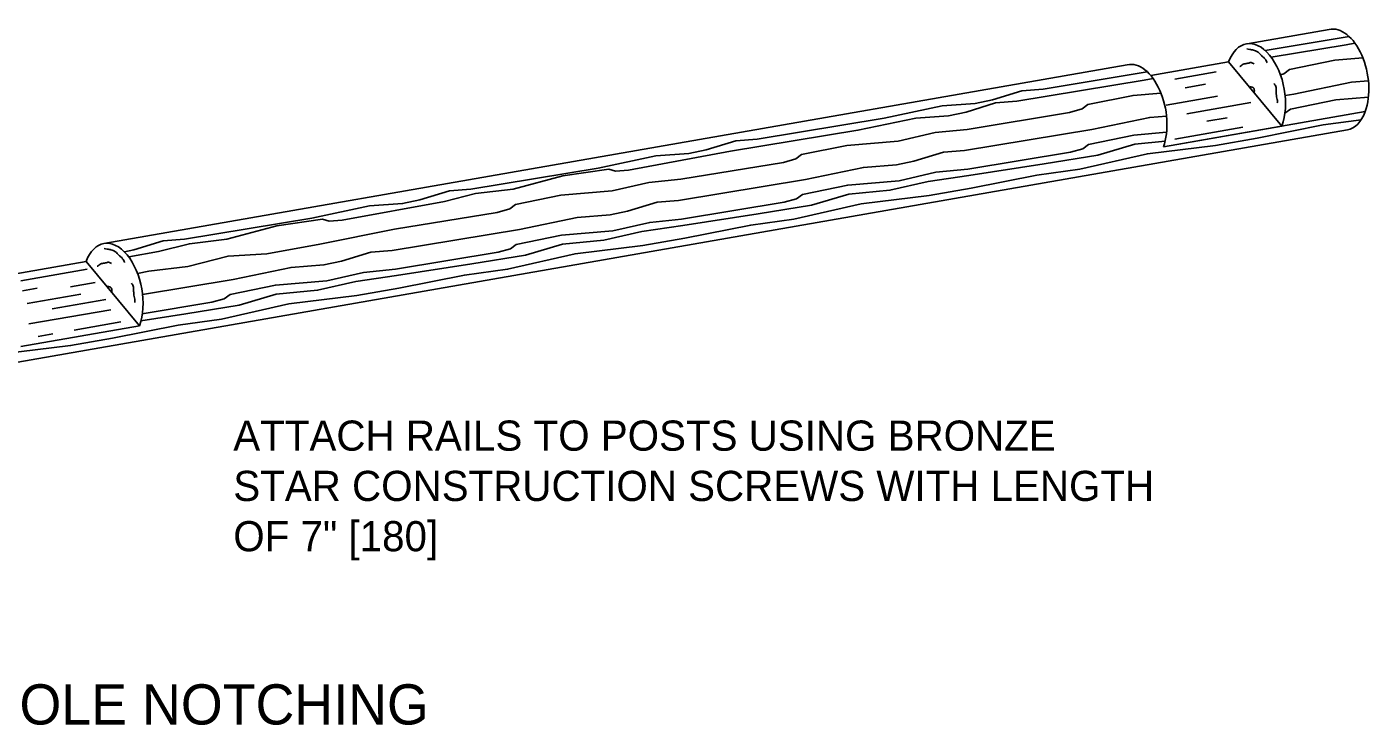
# Model space of a CAD drawing. Extents: x 49991 to 50288, y 49919 to 50011.
# Drawn here: x 50131.11 to 50150.21, y 49960.39 to 49970.31 of the extents above; entities that cross this region are included whole.
import ezdxf

# ---------------------------------------------------------------- set-up
doc = ezdxf.new("R2010")
doc.units = 0
doc.layers.add('Level 1', color=7, linetype='Continuous')
doc.layers.add('Level 2', color=7, linetype='Continuous')

msp = doc.modelspace()

# ---------------------------------------------------------------- linework, layer by layer
at = {"layer": 'Level 1'}
for p, q in [((50148.45032095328, 49970.06973190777), (50149.616370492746, 49970.27344752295)), ((50132.20796831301, 49967.23209650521), (50146.74800530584, 49969.772325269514)), ((50148.18814838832, 49969.811157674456), (50147.083473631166, 49969.618284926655)), ((50147.08368423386, 49969.618209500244), (50148.18814838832, 49969.811157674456)), ((50148.18828656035, 49969.8111817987), (50148.9467034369, 49968.90097008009)), ((50147.42499742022, 49969.56718812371), (50148.01425804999, 49969.67006959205)), ((50147.57207015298, 49969.445268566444), (50147.861148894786, 49969.49553878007)), ((50147.30407706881, 49969.198929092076), (50148.030781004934, 49969.32585033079)), ((50147.596818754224, 49969.07687578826), (50148.50698885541, 49969.23559233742)), ((50147.262093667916, 49968.606609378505), (50150.130656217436, 49969.10774276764)), ((50147.87966226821, 49968.969568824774), (50148.168741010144, 49969.019839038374)), ((50113.90505239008, 49962.567250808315), (50149.87663416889, 49968.84808164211)), ((50147.262056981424, 49968.606677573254), (50148.9467034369, 49968.90097008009)), ((50147.42451887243, 49968.716225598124), (50148.39337950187, 49968.8854457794)), ((50131.954379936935, 49966.97514372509), (50130.84970517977, 49966.78227097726)), ((50131.96889181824, 49966.86947742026), (50131.02839103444, 49966.70487244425)), ((50131.95451810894, 49966.97516784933), (50132.712934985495, 49966.06495613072)), ((50132.08617606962, 49966.678574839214), (50131.73579811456, 49966.617650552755)), ((50131.26102300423, 49966.59721857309), (50131.05133796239, 49966.56090967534)), ((50131.881565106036, 49966.513987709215), (50131.116986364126, 49966.38074882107)), ((50132.23741644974, 49966.439771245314), (50131.47522511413, 49966.306308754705)), ((50132.30510708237, 49966.293204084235), (50131.141221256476, 49966.08991450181)), ((50131.02828853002, 49965.77066362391), (50132.712934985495, 49966.06495613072)), ((50132.44856788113, 49966.11945066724), (50131.7866710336, 49966.00354967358)), ((50131.484160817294, 49965.94833130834), (50131.27473404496, 49965.911812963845))]:
    msp.add_line(p, q, dxfattribs=at)
for points in [[(50148.70739651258, 49969.97515538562), (50149.902069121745, 49970.172291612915)], [(50148.79570268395, 49969.8778573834), (50149.857548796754, 49970.05298712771), (50149.983376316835, 49970.07959688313)], [(50148.92511135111, 49969.63103608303), (50148.97486510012, 49969.64477204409), (50149.0563922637, 49969.70623738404), (50149.70032202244, 49969.83799336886), (50150.09613885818, 49969.87127311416)], [(50145.18110421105, 49969.25368066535), (50146.988986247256, 49969.551853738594), (50147.114813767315, 49969.57846349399)], [(50145.55565291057, 49969.42729350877), (50147.03350657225, 49969.6711582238)], [(50148.99181456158, 49969.334903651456), (50149.11338977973, 49969.35497671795), (50149.93641159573, 49969.52623111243), (50150.17539683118, 49969.544558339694)], [(50141.48827417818, 49968.71619301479), (50143.29629242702, 49969.0153259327), (50144.118637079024, 49969.18627323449), (50144.58559179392, 49969.22201420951), (50144.8330862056, 49969.27432659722), (50145.251976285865, 49969.40363187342), (50145.55565291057, 49969.42729350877)], [(50144.47193565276, 49968.854594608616), (50145.93005781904, 49969.09498120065), (50146.1063025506, 49969.14363865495), (50146.1878297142, 49969.20510399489), (50146.83175947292, 49969.336859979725), (50147.22757630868, 49969.37013972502)], [(50148.98955932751, 49969.08277762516), (50149.068641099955, 49969.14274059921), (50149.71308739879, 49969.27407769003), (50150.17617772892, 49969.31325724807)], [(50141.11367665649, 49968.54304788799), (50142.92148545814, 49968.841922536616), (50143.74383011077, 49969.0128698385), (50144.21106750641, 49969.048167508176), (50144.45832805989, 49969.10045548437), (50144.87789530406, 49969.23006785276), (50145.18110421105, 49969.25368066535)], [(50144.43837275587, 49968.555582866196), (50146.24482723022, 49968.853843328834), (50147.06784904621, 49969.02509772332), (50147.30683428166, 49969.04342495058)], [(50148.59656793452, 49968.729591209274), (50149.53098348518, 49968.91625600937), (50150.0720112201, 49968.98975277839)], [(50140.40583801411, 49968.14480987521), (50141.86398459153, 49968.384962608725), (50142.039478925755, 49968.43401454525), (50142.12173207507, 49968.495319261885), (50142.765637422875, 49968.62730910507), (50143.4958781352, 49968.68864208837), (50144.0193219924, 49968.80829389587), (50144.47193565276, 49968.854594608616)], [(50144.48423331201, 49968.29063010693), (50145.94144445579, 49968.530685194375), (50146.118366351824, 49968.57964974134), (50146.200078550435, 49968.64160721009), (50146.84452484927, 49968.772944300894), (50147.3076151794, 49968.81212385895)], [(50144.530567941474, 49968.01887104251), (50145.46428191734, 49968.20546260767), (50146.076036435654, 49968.289888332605), (50147.03514231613, 49968.507262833), (50148.00125139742, 49968.62584118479), (50148.59656793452, 49968.729591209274)], [(50141.11367665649, 49968.54304788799), (50139.660773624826, 49968.2753101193), (50139.47764198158, 49968.26092194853), (50139.38074789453, 49968.29005110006), (50138.73005718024, 49968.195887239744), (50138.02189552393, 49968.00683535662), (50137.48894883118, 49967.94198354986), (50137.047959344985, 49967.83188441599)], [(50137.4214261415, 49968.00680276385), (50139.22954203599, 49968.305000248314), (50140.05181345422, 49968.476649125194), (50140.51834927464, 49968.51187356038), (50140.76589250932, 49968.56371823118), (50141.1854597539, 49968.69333059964), (50141.48827417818, 49968.71619301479)], [(50140.37141291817, 49967.844998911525), (50142.17934377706, 49968.142704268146), (50143.00112306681, 49968.31453818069), (50143.46815101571, 49968.34957758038), (50143.71554778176, 49968.40282540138), (50144.135914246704, 49968.531575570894), (50144.43837275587, 49968.555582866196)], [(50144.499317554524, 49968.20047892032), (50145.570655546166, 49968.36408420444), (50146.32978476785, 49968.486115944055), (50146.85619207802, 49968.64532058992), (50147.28593578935, 49968.68515441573)], [(50140.41753174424, 49967.57983670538), (50141.87476729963, 49967.819657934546), (50142.05140651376, 49967.86906578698), (50142.1339179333, 49967.93016105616), (50142.777540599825, 49968.06259420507), (50143.50752304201, 49968.12413663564), (50144.03070862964, 49968.24399788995), (50144.48423331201, 49968.29063010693)], [(50140.43259157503, 49967.48991937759), (50141.50346184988, 49967.653475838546), (50142.263477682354, 49967.77607294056), (50142.790586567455, 49967.93535082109), (50143.37697359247, 49967.98875975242), (50143.920309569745, 49968.1126156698), (50144.499317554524, 49968.20047892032)], [(50133.35451512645, 49967.29575109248), (50135.162372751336, 49967.59415802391), (50135.9845953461, 49967.76627461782), (50136.451204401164, 49967.8007974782), (50136.6991177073, 49967.85362640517), (50137.11824164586, 49967.98295609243), (50137.4214261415, 49968.00680276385)], [(50136.339506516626, 49967.435000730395), (50137.79749247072, 49967.67442747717), (50137.97405845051, 49967.724536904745), (50138.05542498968, 49967.78527625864), (50138.699539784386, 49967.91752437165), (50139.42975608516, 49967.97909121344), (50139.95324876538, 49968.09827530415), (50140.40583801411, 49968.14480987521)], [(50140.46451912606, 49967.30861859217), (50141.39849137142, 49967.49500071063), (50142.0097781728, 49967.57937761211), (50142.96878640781, 49967.797687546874), (50143.93426714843, 49967.915491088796), (50144.530567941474, 49968.01887104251)], [(50137.047959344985, 49967.83188441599), (50135.593887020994, 49967.56402458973), (50135.411432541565, 49967.549943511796), (50135.31500617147, 49967.57912148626), (50134.66413042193, 49967.48446549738), (50133.95568608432, 49967.29585691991), (50133.423538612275, 49967.2301429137), (50132.98247589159, 49967.12074535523)], [(50136.30380032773, 49967.13387400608), (50138.111584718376, 49967.43298251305), (50138.934630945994, 49967.60400304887), (50139.40161007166, 49967.639510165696), (50139.64926510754, 49967.69254853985), (50140.06843786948, 49967.82141051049), (50140.37141291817, 49967.844998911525)], [(50136.339506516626, 49967.435000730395), (50135.27679254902, 49967.225014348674), (50134.52167214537, 49967.08496135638), (50133.97257159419, 49967.05482993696), (50133.40128932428, 49966.906543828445), (50132.84835286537, 49966.83842334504), (50132.68714974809, 49966.80646604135)], [(50136.351039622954, 49966.8693015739), (50137.80822635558, 49967.10959051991), (50137.985284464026, 49967.15951491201), (50138.067586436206, 49967.220351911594), (50138.71104847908, 49967.35205907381), (50139.44124036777, 49967.41385977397), (50139.96449919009, 49967.53301945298), (50140.41753174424, 49967.57983670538)], [(50136.36680102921, 49966.779457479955), (50137.437227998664, 49966.94273126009), (50138.197219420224, 49967.065562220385), (50138.723675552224, 49967.22429914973), (50139.310101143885, 49967.27960335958), (50139.854051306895, 49967.40210494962), (50140.43259157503, 49967.48991937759)], [(50132.499412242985, 49967.11476491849), (50132.63241613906, 49967.14283300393), (50133.051306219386, 49967.27213827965), (50133.35451512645, 49967.29575109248)], [(50136.39870416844, 49966.598390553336), (50137.33174098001, 49966.784675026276), (50137.94345693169, 49966.86720547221), (50138.90273759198, 49967.08743509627), (50139.867984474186, 49967.20521422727), (50140.46451912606, 49967.30861859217)], [(50132.98247589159, 49967.12074535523), (50132.56102159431, 49967.04318186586)], [(50132.75715391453, 49966.50951816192), (50134.04623747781, 49966.72280329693), (50134.86904984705, 49966.89379942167), (50135.33556125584, 49966.929257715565), (50135.58298243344, 49966.982271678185), (50136.00171188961, 49967.11085096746), (50136.30380032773, 49967.13387400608)], [(50132.75443597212, 49966.23644659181), (50133.74287911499, 49966.39941130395), (50133.91928447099, 49966.44879474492), (50134.00067542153, 49966.509300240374), (50134.64476580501, 49966.64178221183), (50135.37477265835, 49966.70309078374), (50135.8987086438, 49966.822557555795), (50136.351039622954, 49966.8693015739)], [(50132.73471223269, 49966.13510606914), (50133.37076028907, 49966.23196226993), (50134.13062965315, 49966.355962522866), (50134.656740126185, 49966.51348133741), (50135.24452004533, 49966.56939973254), (50135.78826076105, 49966.69164305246), (50136.36680102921, 49966.779457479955)], [(50132.33078448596, 49965.88794281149), (50133.26548271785, 49966.07416430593), (50133.87756874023, 49966.157679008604), (50134.83678642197, 49966.37624721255), (50135.80219392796, 49966.49475232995), (50136.39870416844, 49966.598390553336)], [(50128.26501835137, 49965.177247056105), (50129.19945831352, 49965.36367799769), (50129.8097608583, 49965.44842497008), (50130.769358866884, 49965.665614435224), (50131.7343230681, 49965.783836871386), (50132.33078448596, 49965.88794281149)]]:
    msp.add_lwpolyline(points, dxfattribs=at)
for centre, start_param, end_param in [((50149.7510591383, 49969.561881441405), 3.9254893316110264, 6.306125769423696), ((50148.56712636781, 49969.354986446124), 3.9256121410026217, 7.063370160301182), ((50146.88249658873, 49969.06074805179), 3.9254893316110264, 6.306125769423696), ((50149.75087589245, 49969.561380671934), 3.1414661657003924, 3.926391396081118), ((50132.33335791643, 49966.51897249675), 3.9256121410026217, 7.063370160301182)]:
    msp.add_ellipse(centre, major_axis=(-0.12527116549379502, 0.7134132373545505), ratio=0.577493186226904, start_param=start_param, end_param=end_param, dxfattribs=at)
for points in [[(50148.44594680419, 49969.9983371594), (50148.48856031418, 49969.990965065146), (50148.54244395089, 49969.97980487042), (50148.57335038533, 49969.96908306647), (50148.60789310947, 49969.95070301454), (50148.63103585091, 49969.9282960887), (50148.65402822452, 49969.90280018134), (50148.689226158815, 49969.8736138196), (50148.70055146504, 49969.86250287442), (50148.71608868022, 49969.84048407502), (50148.7314472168, 49969.811118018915), (50148.73519140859, 49969.800161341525)], [(50148.34731576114, 49969.745468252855), (50148.358465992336, 49969.753376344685), (50148.41050775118, 49969.78396917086), (50148.463262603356, 49969.79392575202), (50148.508824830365, 49969.80239070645), (50148.55089433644, 49969.78633411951)], [(50148.88055680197, 49969.22972903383), (50148.88411294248, 49969.262173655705), (50148.87614924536, 49969.29627455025), (50148.86540759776, 49969.37881455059), (50148.863781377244, 49969.400683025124), (50148.859135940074, 49969.46417207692), (50148.832605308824, 49969.50745972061)], [(50148.48711410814, 49969.45254483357), (50148.48745187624, 49969.45281574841), (50148.4880433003, 49969.45328310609), (50148.489800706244, 49969.45450617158), (50148.491626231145, 49969.45549138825), (50148.49544834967, 49969.456820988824), (50148.497431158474, 49969.45720134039), (50148.49944742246, 49969.45743801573), (50148.50354382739, 49969.45742585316), (50148.50564110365, 49969.45722147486), (50148.50770888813, 49969.45697017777), (50148.50975745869, 49969.45665553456), (50148.51179709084, 49969.45626111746), (50148.515816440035, 49969.45537871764), (50148.51967549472, 49969.45449019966), (50148.52226387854, 49969.45388149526), (50148.52483623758, 49969.45319498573), (50148.529904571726, 49969.451440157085), (50148.53482387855, 49969.448928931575), (50148.53720995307, 49969.4472969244), (50148.53838150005, 49969.44637059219), (50148.539537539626, 49969.44536452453), (50148.54248429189, 49969.442523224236), (50148.545154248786, 49969.43960652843), (50148.54748220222, 49969.43665320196), (50148.54854980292, 49969.43510371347), (50148.549564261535, 49969.433500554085), (50148.551250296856, 49969.430306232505), (50148.55256854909, 49969.42695380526), (50148.55348134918, 49969.423486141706), (50148.5539680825, 49969.41987348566), (50148.55442319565, 49969.41132365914), (50148.554579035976, 49969.40281274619), (50148.55447239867, 49969.39432003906), (50148.55414007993, 49969.385824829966), (50148.55389014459, 49969.380640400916), (50148.553643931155, 49969.37545646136), (50148.553511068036, 49969.37286617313)], [(50132.21217835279, 49967.162323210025), (50132.254791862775, 49967.15495111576), (50132.30867549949, 49967.14379092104), (50132.33958193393, 49967.13306911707), (50132.37412465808, 49967.11468906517), (50132.3972673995, 49967.092282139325), (50132.42025977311, 49967.066786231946), (50132.45545770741, 49967.03759987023), (50132.46678301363, 49967.026488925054), (50132.48232022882, 49967.00447012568), (50132.497678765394, 49966.97510406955), (50132.50142295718, 49966.96414739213)], [(50132.11354730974, 49966.90945430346), (50132.12469754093, 49966.91736239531), (50132.17673929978, 49966.94795522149), (50132.22949415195, 49966.95791180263), (50132.27505637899, 49966.96637675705), (50132.317125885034, 49966.95032017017)], [(50132.64678835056, 49966.39371508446), (50132.65034449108, 49966.42615970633), (50132.64238079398, 49966.46026060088), (50132.631639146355, 49966.542800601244), (50132.630012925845, 49966.56466907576), (50132.625367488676, 49966.62815812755), (50132.59883685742, 49966.67144577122)], [(50132.25334565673, 49966.61653088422), (50132.25368342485, 49966.616801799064), (50132.25427484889, 49966.61726915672), (50132.25603225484, 49966.61849222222), (50132.25785777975, 49966.61947743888), (50132.26167989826, 49966.62080703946), (50132.26366270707, 49966.62118739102), (50132.26567897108, 49966.621424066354), (50132.269775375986, 49966.62141190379), (50132.27187265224, 49966.621207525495), (50132.273940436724, 49966.6209562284), (50132.275989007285, 49966.620641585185), (50132.27802863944, 49966.62024716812), (50132.28204798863, 49966.61936476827), (50132.28590704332, 49966.61847625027), (50132.288495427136, 49966.617867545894), (50132.29106778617, 49966.61718103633), (50132.29613612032, 49966.61542620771), (50132.301055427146, 49966.6129149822), (50132.30344150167, 49966.611282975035), (50132.304613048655, 49966.61035664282), (50132.30576908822, 49966.60935057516), (50132.30871584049, 49966.60650927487), (50132.31138579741, 49966.60359257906), (50132.31371375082, 49966.60063925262), (50132.314781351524, 49966.59908976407), (50132.31579581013, 49966.597486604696), (50132.31748184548, 49966.59429228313), (50132.31880009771, 49966.590939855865), (50132.31971289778, 49966.58747219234), (50132.320199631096, 49966.583859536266), (50132.320654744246, 49966.57530970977), (50132.32081058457, 49966.5667987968), (50132.32070394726, 49966.55830608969), (50132.32037162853, 49966.54981088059), (50132.320121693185, 49966.54462645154), (50132.31987547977, 49966.53944251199), (50132.31974261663, 49966.536852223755)]]:
    msp.add_spline(points, degree=3, dxfattribs=at)

# ---------------------------------------------------------------- texts
at = {"layer": 'Level 2'}
for s, height, p in [('ATTACH RAILS TO POSTS USING BRONZE ', 0.4285227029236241, (50134.04699509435, 49964.28999256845)), ('STAR CONSTRUCTION SCREWS WITH LENGTH', 0.4285227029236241, (50134.04699509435, 49963.57578806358)), ('OF 7" [180]', 0.4285227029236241, (50134.04699509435, 49962.861583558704)), ('BRACE POLE NOTCHING', 0.5713636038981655, (50127.65499290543, 49960.40062793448))]:
    msp.add_text(s, height=height, dxfattribs=at).set_placement(p)

doc.saveas('drawing.dxf')
